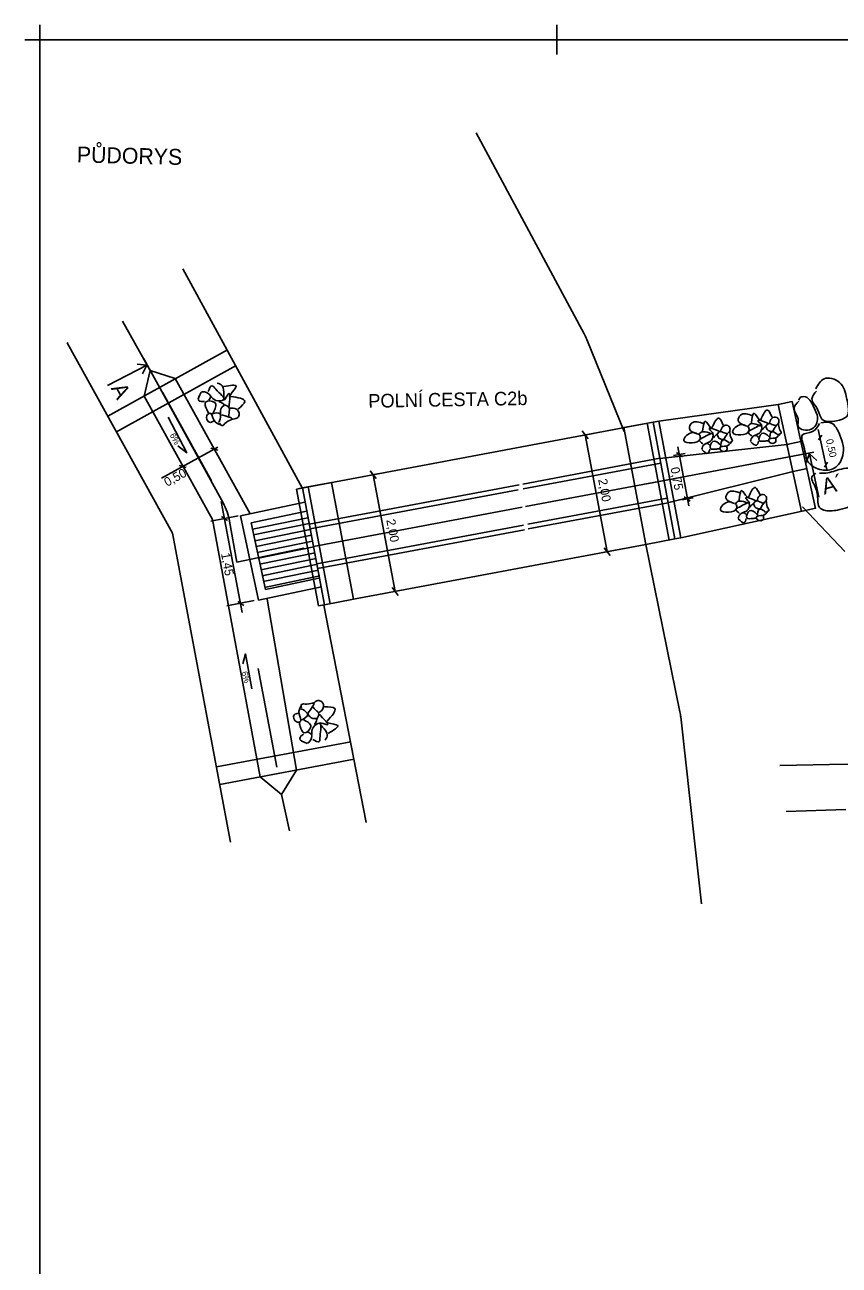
# Model space of a CAD drawing. Extents: x -463095.2 to -463031, y -1105061.3 to -1104976.3.
# Drawn here: x -463091.37 to -463063.97, y -1105018.06 to -1104976.31 of the extents above; entities that cross this region are included whole.
import ezdxf

# ---------------------------------------------------------------- set-up
doc = ezdxf.new("R2010")
doc.units = 0
for name, color, linetype in [('Implicitní', 7, 'Continuous'), ('Vrstva 14', 7, 'Continuous'), ('Vrstva 57', 7, 'Continuous')]:
    doc.layers.add(name, color=color, linetype=linetype)

msp = doc.modelspace()

# ---------------------------------------------------------------- linework, layer by layer
at = {"layer": 'Implicitní'}
for p, q in [((-463073.467, -1104976.311), (-463073.467, -1104977.311)), ((-463073.467, -1104976.311), (-463073.467, -1104977.311)), ((-463073.467, -1104976.311), (-463073.467, -1104977.311)), ((-463073.467, -1104976.311), (-463073.467, -1104977.311)), ((-463072.967, -1104976.811), (-463073.967, -1104976.811)), ((-463072.967, -1104976.811), (-463073.967, -1104976.811)), ((-463072.967, -1104976.811), (-463073.967, -1104976.811)), ((-463072.967, -1104976.811), (-463073.967, -1104976.811))]:
    msp.add_line(p, q, dxfattribs=at)
at = {"layer": 'Vrstva 14'}
for p, q in [((-463090.867, -1104976.311), (-463090.867, -1104977.311)), ((-463090.867, -1104976.311), (-463090.867, -1104977.311)), ((-463090.867, -1104976.312), (-463090.867, -1104977.312)), ((-463091.367, -1104976.811), (-463090.367, -1104976.811)), ((-463091.367, -1104976.811), (-463090.367, -1104976.811)), ((-463091.367, -1104976.812), (-463090.367, -1104976.812)), ((-463072.552, -1104986.71), (-463076.182, -1104979.944)), ((-463082.033, -1104991.9), (-463086.05, -1104984.519)), ((-463087.151, -1104987.945), (-463088.076, -1104986.286)), ((-463071.202, -1104990.001), (-463072.461, -1104986.903)), ((-463084.553, -1104987.255), (-463088.579, -1104989.479)), ((-463087.369, -1104987.55), (-463084.698, -1104992.406)), ((-463084.262, -1104987.782), (-463088.288, -1104990.006)), ((-463087.263, -1104987.762), (-463087.413, -1104988.063)), ((-463086.725, -1104988.7), (-463085.088, -1104991.663)), ((-463066.021, -1104989.094), (-463070.038, -1104989.647)), ((-463065.552, -1104988.991), (-463066.021, -1104989.094)), ((-463066.021, -1104989.094), (-463065.235, -1104992.689)), ((-463065.552, -1104988.991), (-463064.766, -1104992.586)), ((-463082.225, -1104991.937), (-463070.224, -1104989.682)), ((-463071.217, -1104989.868), (-463070.234, -1104989.684)), ((-463070.431, -1104989.721), (-463069.692, -1104993.652)), ((-463070.234, -1104989.684), (-463070.038, -1104989.647)), ((-463070.234, -1104989.684), (-463069.495, -1104993.615)), ((-463070.038, -1104989.647), (-463069.299, -1104993.578)), ((-463072.249, -1104990.062), (-463072.664, -1104990.14)), ((-463072.618, -1104989.979), (-463072.415, -1104990.246)), ((-463071.778, -1104994.044), (-463072.516, -1104990.113)), ((-463071.217, -1104989.868), (-463070.478, -1104993.8)), ((-463064.389, -1104991.275), (-463064.683, -1104989.931)), ((-463064.559, -1104990.118), (-463064.665, -1104990.285)), ((-463086.773, -1104991.571), (-463084.878, -1104990.524)), ((-463084.872, -1104990.63), (-463085.111, -1104990.563)), ((-463065.721, -1104990.436), (-463070.007, -1104990.91)), ((-463069.399, -1104990.515), (-463069.033, -1104992.5)), ((-463065.261, -1104990.336), (-463065.73, -1104990.438)), ((-463074.619, -1104991.769), (-463070.005, -1104990.902)), ((-463069.54, -1104990.808), (-463069.158, -1104990.738)), ((-463069.241, -1104990.851), (-463069.444, -1104990.709)), ((-463064.972, -1104990.749), (-463064.721, -1104990.973)), ((-463085.934, -1104991.21), (-463086.172, -1104991.143)), ((-463079.749, -1104991.319), (-463079.546, -1104991.587)), ((-463074.599, -1104991.928), (-463069.976, -1104991.06)), ((-463065.522, -1104991.345), (-463069.708, -1104992.393)), ((-463065.053, -1104991.242), (-463065.522, -1104991.345)), ((-463064.364, -1104991.031), (-463064.47, -1104991.199)), ((-463081.045, -1104991.716), (-463082.028, -1104991.9)), ((-463074.736, -1104991.792), (-463081.799, -1104993.119)), ((-463081.045, -1104991.716), (-463080.306, -1104995.647)), ((-463080.013, -1104991.522), (-463079.5, -1104991.425)), ((-463078.909, -1104995.384), (-463079.648, -1104991.453)), ((-463074.523, -1104992.525), (-463069.865, -1104991.649)), ((-463082.224, -1104991.937), (-463082.028, -1104991.9)), ((-463082.224, -1104991.937), (-463081.486, -1104995.868)), ((-463082.028, -1104991.9), (-463081.289, -1104995.832)), ((-463081.831, -1104991.863), (-463081.092, -1104995.795)), ((-463074.776, -1104991.962), (-463081.769, -1104993.276)), ((-463074.45, -1104993.122), (-463069.754, -1104992.239)), ((-463069.265, -1104992.303), (-463068.883, -1104992.233)), ((-463068.981, -1104992.344), (-463069.184, -1104992.202)), ((-463084.055, -1104996.094), (-463084.759, -1104992.351)), ((-463084.111, -1104992.843), (-463081.945, -1104992.381)), ((-463074.631, -1104992.545), (-463081.658, -1104993.866)), ((-463074.43, -1104993.281), (-463069.725, -1104992.396)), ((-463069.299, -1104993.578), (-463064.76, -1104992.585)), ((-463063.779, -1104994.043), (-463065.206, -1104992.538)), ((-463084.188, -1104992.842), (-463085.108, -1104993.015)), ((-463084.749, -1104992.856), (-463084.546, -1104992.997)), ((-463083.507, -1104995.679), (-463084.111, -1104992.843)), ((-463083.754, -1104993.073), (-463081.891, -1104992.676)), ((-463083.275, -1104995.323), (-463083.754, -1104993.073)), ((-463081.846, -1104992.903), (-463083.711, -1104993.287)), ((-463084.447, -1105003.822), (-463086.403, -1104993.42)), ((-463081.805, -1104993.099), (-463083.67, -1104993.483)), ((-463081.765, -1104993.295), (-463083.63, -1104993.678)), ((-463081.725, -1104993.49), (-463083.59, -1104993.874)), ((-463074.589, -1104993.148), (-463081.548, -1104994.456)), ((-463074.56, -1104993.305), (-463081.518, -1104994.613)), ((-463081.684, -1104993.686), (-463083.549, -1104994.07)), ((-463081.644, -1104993.882), (-463083.509, -1104994.266)), ((-463070.478, -1104993.8), (-463080.306, -1104995.647)), ((-463070.478, -1104993.8), (-463069.495, -1104993.615)), ((-463070.478, -1104993.8), (-463069.331, -1104999.43)), ((-463069.495, -1104993.615), (-463069.299, -1104993.578)), ((-463081.604, -1104994.078), (-463083.469, -1104994.462)), ((-463081.563, -1104994.274), (-463083.428, -1104994.658)), ((-463071.51, -1104993.993), (-463071.925, -1104994.071)), ((-463071.676, -1104994.177), (-463071.879, -1104993.91)), ((-463081.523, -1104994.47), (-463083.388, -1104994.854)), ((-463081.483, -1104994.666), (-463083.348, -1104995.05)), ((-463081.442, -1104994.862), (-463083.307, -1104995.246)), ((-463083.275, -1104995.323), (-463081.472, -1104994.939)), ((-463083.507, -1104995.679), (-463081.39, -1104995.228)), ((-463079.274, -1104995.453), (-463078.761, -1104995.356)), ((-463078.807, -1104995.518), (-463079.01, -1104995.251)), ((-463083.653, -1104995.692), (-463084.573, -1104995.865)), ((-463084.2, -1104995.716), (-463083.996, -1104995.857)), ((-463081.486, -1104995.868), (-463081.289, -1104995.832)), ((-463081.307, -1104995.845), (-463079.886, -1105003.155)), ((-463080.306, -1104995.647), (-463081.289, -1104995.832)), ((-463082.886, -1105001.301), (-463083.512, -1104997.973)), ((-463069.303, -1104999.609), (-463068.828, -1105003.882)), ((-463080.403, -1105000.44), (-463084.923, -1105001.289)), ((-463080.291, -1105001.031), (-463084.812, -1105001.881)), ((-463082.727, -1105002.219), (-463082.459, -1105003.444)), ((-463063.745, -1105002.725), (-463065.755, -1105002.785)), ((-463068.828, -1105003.882), (-463068.604, -1105005.901))]:
    msp.add_line(p, q, dxfattribs=at)
msp.add_lwpolyline([(-463090.867, -1105060.811), (-463090.867, -1104976.812), (-463031.467, -1104976.812), (-463031.467, -1105060.811)], close=True, dxfattribs=at)
for points in [[(-463089.924, -1104987.024), (-463089.939, -1104987.018), (-463086.403, -1104993.42)], [(-463088.587, -1104988.454), (-463087.263, -1104987.762), (-463087.588, -1104987.728)], [(-463087.151, -1104987.945), (-463087.35, -1104988.805), (-463085.055, -1104992.965)], [(-463087.151, -1104987.945), (-463086.304, -1104988.221), (-463083.789, -1104992.775)], [(-463086.544, -1104989.518), (-463085.919, -1104990.714), (-463086.223, -1104990.485)], [(-463070.387, -1104991.745), (-463064.826, -1104990.694)], [(-463064.653, -1104992.208), (-463064.972, -1104990.749), (-463065.091, -1104991.053)], [(-463082.727, -1105002.219), (-463083.454, -1105001.624), (-463085.055, -1104992.965)], [(-463084.481, -1104993.017), (-463084.235, -1104994.393), (-463081.986, -1104993.931)], [(-463082.727, -1105002.219), (-463082.231, -1105001.396), (-463083.216, -1104995.642)], [(-463083.727, -1104998.656), (-463083.944, -1104997.484), (-463084.028, -1104997.822)], [(-463065.972, -1105001.24), (-463063.741, -1105001.201), (-463054.531, -1105001.611)]]:
    msp.add_lwpolyline(points, dxfattribs=at)
for centre, start, end in [((-463074.314, -1104987.656), 22.1223, 28.2143), ((-463086.45, -1104993.37), 10.1509, 28.8207), ((-463071.291, -1104999.83), 6.3401, 11.5166)]:
    msp.add_arc(centre, 2, start, end, dxfattribs=at)
for points in [[(-463085.2, -1104988.652), (-463085.074, -1104988.462), (-463084.943, -1104988.579), (-463084.68, -1104988.932), (-463084.939, -1104988.954), (-463085.12, -1104988.797)], [(-463084.499, -1104989.209), (-463084.519, -1104988.735), (-463084.653, -1104988.931), (-463084.726, -1104988.459), (-463084.893, -1104988.376)], [(-463084.672, -1104988.482), (-463084.253, -1104988.481), (-463084.449, -1104988.763), (-463084.478, -1104988.834)], [(-463064.736, -1104988.638), (-463064.888, -1104988.896), (-463064.687, -1104989.276), (-463064.553, -1104989.583), (-463064.063, -1104989.637), (-463063.715, -1104989.49), (-463063.715, -1104988.91), (-463063.96, -1104988.352), (-463064.482, -1104988.227), (-463064.759, -1104988.566)], [(-463085.324, -1104988.99), (-463085.516, -1104988.961), (-463085.433, -1104988.673)], [(-463085.172, -1104988.947), (-463085.124, -1104988.814), (-463085.325, -1104988.669), (-463085.422, -1104988.668)], [(-463084.436, -1104988.822), (-463083.967, -1104988.986), (-463084.201, -1104989.248)], [(-463065.328, -1104988.978), (-463065.489, -1104989.223), (-463065.351, -1104989.576), (-463065.351, -1104989.825), (-463064.909, -1104989.919), (-463064.7, -1104989.611), (-463064.833, -1104989.165), (-463065.159, -1104988.826), (-463065.309, -1104988.885), (-463065.325, -1104988.941)], [(-463085.029, -1104989.38), (-463084.979, -1104989.028), (-463085.285, -1104989.01), (-463085.245, -1104989.257), (-463085.181, -1104989.398)], [(-463084.831, -1104989.001), (-463084.663, -1104989.112), (-463084.75, -1104989.199), (-463084.783, -1104989.407)], [(-463084.692, -1104989.091), (-463084.477, -1104989.224), (-463084.49, -1104989.325), (-463084.497, -1104989.532)], [(-463084.487, -1104989.218), (-463084.25, -1104989.247), (-463084.158, -1104989.438), (-463084.232, -1104989.548), (-463084.409, -1104989.579)], [(-463066.61, -1104989.603), (-463066.378, -1104989.281), (-463066.23, -1104989.52)], [(-463084.769, -1104989.776), (-463085.008, -1104989.611), (-463085.134, -1104989.384), (-463085.242, -1104989.457), (-463085.154, -1104989.691), (-463085.007, -1104989.638)], [(-463085.117, -1104989.415), (-463084.794, -1104989.413), (-463084.816, -1104989.64), (-463084.852, -1104989.7)], [(-463084.782, -1104989.434), (-463084.401, -1104989.586), (-463084.597, -1104989.694), (-463084.741, -1104989.802), (-463084.813, -1104989.72)], [(-463068.715, -1104990.088), (-463069.011, -1104989.895), (-463068.938, -1104989.721), (-463068.519, -1104989.74)], [(-463068.566, -1104989.977), (-463068.471, -1104989.654), (-463068.299, -1104989.869), (-463068.251, -1104989.908)], [(-463068.251, -1104989.873), (-463068.018, -1104989.551), (-463067.871, -1104989.79)], [(-463067.074, -1104989.818), (-463067.37, -1104989.626), (-463067.297, -1104989.451), (-463066.879, -1104989.47)], [(-463066.328, -1104989.74), (-463066.696, -1104989.647), (-463066.577, -1104989.794), (-463066.955, -1104989.743), (-463067.057, -1104989.852)], [(-463066.925, -1104989.707), (-463066.83, -1104989.385), (-463066.659, -1104989.599), (-463066.611, -1104989.638)], [(-463066.462, -1104989.861), (-463066.312, -1104989.726), (-463066.237, -1104989.759), (-463066.08, -1104989.812)], [(-463066.318, -1104989.733), (-463066.242, -1104989.557), (-463066.074, -1104989.53), (-463066.007, -1104989.612), (-463066.024, -1104989.755)], [(-463066.22, -1104990.008), (-463066.016, -1104989.75), (-463065.978, -1104989.925), (-463065.929, -1104990.06), (-463066.008, -1104990.097)], [(-463064.638, -1104989.731), (-463064.865, -1104989.999), (-463065.208, -1104990.115), (-463065.159, -1104990.507), (-463064.999, -1104991.047), (-463064.553, -1104991.288), (-463064.143, -1104991.239), (-463063.848, -1104990.806), (-463063.947, -1104990.128), (-463064.259, -1104989.704), (-463064.589, -1104989.704)], [(-463068.658, -1104990.123), (-463068.647, -1104990.248), (-463069.193, -1104990.304), (-463068.902, -1104990.032), (-463068.748, -1104990.079)], [(-463067.969, -1104990.01), (-463068.336, -1104989.917), (-463068.217, -1104990.064), (-463068.595, -1104990.013), (-463068.698, -1104990.122)], [(-463068.555, -1104990.42), (-463068.673, -1104990.28), (-463068.553, -1104990.206), (-463068.223, -1104990.085), (-463068.265, -1104990.289), (-463068.426, -1104990.391)], [(-463068.204, -1104990.217), (-463068.08, -1104990.113), (-463068.034, -1104990.199), (-463067.882, -1104990.272)], [(-463068.103, -1104990.131), (-463067.952, -1104989.996), (-463067.878, -1104990.029), (-463067.72, -1104990.082)], [(-463067.959, -1104990.003), (-463067.883, -1104989.827), (-463067.715, -1104989.8), (-463067.648, -1104989.882), (-463067.664, -1104990.025)], [(-463067.861, -1104990.278), (-463067.657, -1104990.02), (-463067.619, -1104990.195), (-463067.569, -1104990.33), (-463067.648, -1104990.367)], [(-463067.018, -1104989.853), (-463067.007, -1104989.978), (-463067.553, -1104990.034), (-463067.262, -1104989.762), (-463067.108, -1104989.809)], [(-463066.915, -1104990.15), (-463067.032, -1104990.01), (-463066.913, -1104989.936), (-463066.582, -1104989.815), (-463066.624, -1104990.019), (-463066.785, -1104990.122)], [(-463066.682, -1104990.196), (-463066.774, -1104990.129), (-463066.931, -1104990.25), (-463066.954, -1104990.324)], [(-463066.318, -1104990.185), (-463066.576, -1104990.066), (-463066.66, -1104990.297), (-463066.461, -1104990.323), (-463066.339, -1104990.306)], [(-463066.563, -1104989.947), (-463066.44, -1104989.843), (-463066.393, -1104989.929), (-463066.241, -1104990.003)], [(-463065.955, -1104990.076), (-463066.136, -1104990.222), (-463066.339, -1104990.266), (-463066.308, -1104990.366), (-463066.108, -1104990.352), (-463066.115, -1104990.227)], [(-463066.311, -1104990.26), (-463066.239, -1104990.012), (-463066.07, -1104990.081), (-463066.032, -1104990.122)], [(-463068.323, -1104990.466), (-463068.414, -1104990.399), (-463068.571, -1104990.52), (-463068.594, -1104990.594)], [(-463067.958, -1104990.455), (-463068.217, -1104990.336), (-463068.3, -1104990.567), (-463068.102, -1104990.592), (-463067.979, -1104990.575)], [(-463067.596, -1104990.346), (-463067.776, -1104990.492), (-463067.98, -1104990.536), (-463067.948, -1104990.636), (-463067.748, -1104990.622), (-463067.756, -1104990.497)], [(-463067.952, -1104990.53), (-463067.88, -1104990.282), (-463067.711, -1104990.351), (-463067.672, -1104990.392)], [(-463066.684, -1104990.322), (-463066.75, -1104990.463), (-463066.952, -1104990.333)], [(-463068.325, -1104990.592), (-463068.39, -1104990.733), (-463068.592, -1104990.603)], [(-463064.754, -1104991.408), (-463064.883, -1104991.502), (-463064.78, -1104991.859), (-463064.691, -1104992.323), (-463064.642, -1104992.542), (-463064.491, -1104992.644), (-463064.031, -1104992.644), (-463063.394, -1104992.394), (-463063.131, -1104991.993), (-463063.131, -1104991.654), (-463063.389, -1104991.284), (-463063.969, -1104991.284), (-463064.486, -1104991.404), (-463064.629, -1104991.404)], [(-463067.488, -1104992.422), (-463067.784, -1104992.23), (-463067.71, -1104992.055), (-463067.292, -1104992.075)], [(-463066.741, -1104992.344), (-463067.109, -1104992.251), (-463066.99, -1104992.398), (-463067.368, -1104992.347), (-463067.47, -1104992.456)], [(-463067.338, -1104992.311), (-463067.243, -1104991.989), (-463067.072, -1104992.203), (-463067.024, -1104992.242)], [(-463067.024, -1104992.208), (-463066.791, -1104991.885), (-463066.644, -1104992.125)], [(-463066.732, -1104992.337), (-463066.655, -1104992.161), (-463066.488, -1104992.135), (-463066.42, -1104992.217), (-463066.437, -1104992.359)], [(-463067.431, -1104992.457), (-463067.42, -1104992.583), (-463067.966, -1104992.638), (-463067.675, -1104992.367), (-463067.521, -1104992.413)], [(-463067.328, -1104992.754), (-463067.446, -1104992.614), (-463067.326, -1104992.541), (-463066.995, -1104992.419), (-463067.037, -1104992.623), (-463067.198, -1104992.726)], [(-463066.731, -1104992.789), (-463066.989, -1104992.67), (-463067.073, -1104992.901), (-463066.874, -1104992.927), (-463066.752, -1104992.91)], [(-463066.976, -1104992.551), (-463066.853, -1104992.447), (-463066.806, -1104992.534), (-463066.655, -1104992.607)], [(-463066.875, -1104992.465), (-463066.725, -1104992.331), (-463066.65, -1104992.364), (-463066.493, -1104992.416)], [(-463066.724, -1104992.864), (-463066.652, -1104992.616), (-463066.483, -1104992.686), (-463066.445, -1104992.726)], [(-463066.634, -1104992.612), (-463066.43, -1104992.355), (-463066.391, -1104992.53), (-463066.342, -1104992.665), (-463066.421, -1104992.701)], [(-463067.095, -1104992.8), (-463067.187, -1104992.733), (-463067.344, -1104992.854), (-463067.367, -1104992.928)], [(-463067.097, -1104992.926), (-463067.163, -1104993.067), (-463067.365, -1104992.937)], [(-463066.368, -1104992.68), (-463066.549, -1104992.826), (-463066.752, -1104992.871), (-463066.721, -1104992.97), (-463066.521, -1104992.956), (-463066.528, -1104992.831)], [(-463082.063, -1104999.225), (-463082.143, -1104999.505), (-463082.095, -1104999.76), (-463082.225, -1104999.773), (-463082.306, -1104999.536), (-463082.159, -1104999.484)], [(-463082.102, -1104999.725), (-463081.851, -1104999.521), (-463082.014, -1104999.361), (-463082.079, -1104999.336)], [(-463081.856, -1104999.498), (-463081.659, -1104999.137), (-463081.879, -1104999.179), (-463082.058, -1104999.188), (-463082.062, -1104999.296)], [(-463081.569, -1104999.704), (-463081.487, -1104999.465), (-463081.561, -1104999.396), (-463081.698, -1104999.24)], [(-463081.491, -1104999.476), (-463081.327, -1104999.303), (-463081.378, -1104999.096), (-463081.505, -1104999.059), (-463081.661, -1104999.148)], [(-463081.2, -1104999.749), (-463080.942, -1104999.324), (-463081.29, -1104999.271)], [(-463082.012, -1104999.696), (-463081.749, -1104999.936), (-463081.974, -1105000.145), (-463082.1, -1104999.928), (-463082.141, -1104999.779)], [(-463081.618, -1104999.862), (-463081.559, -1104999.67), (-463081.681, -1104999.658), (-463081.839, -1104999.519)], [(-463081.495, -1104999.491), (-463081.208, -1104999.868), (-463081.436, -1104999.803), (-463081.192, -1105000.213), (-463081.268, -1105000.384)], [(-463081.846, -1105000.121), (-463081.725, -1105000.194), (-463081.788, -1105000.433), (-463081.861, -1105000.496)], [(-463081.68, -1105000.366), (-463081.462, -1105000.433), (-463081.436, -1105000.259), (-463081.457, -1104999.82), (-463081.672, -1104999.968), (-463081.711, -1105000.203)], [(-463081.165, -1105000.162), (-463080.841, -1104999.895), (-463081.172, -1104999.803), (-463081.239, -1104999.767)], [(-463081.991, -1105000.185), (-463082.121, -1105000.329), (-463081.873, -1105000.498)]]:
    msp.add_spline(points, degree=3, dxfattribs=at)

# ---------------------------------------------------------------- texts
for s, height, rotation, p in [('PŮDORYS', 0.536, 358.5898, (-463089.622, -1104980.942)), ('A', 0.536, 297.5844, (-463088.481, -1104988.541)), ('0,50', 0.24, 282.3388, (-463064.419, -1104990.279)), ('0,50', 0.3, 28.9139, (-463086.579, -1104991.864)), ('0,75', 0.3, 280.4302, (-463069.648, -1104991.226)), ('2,00', 0.3, 280.6452, (-463072.081, -1104991.619)), ('A´', 0.536, 14.398, (-463064.48, -1104992.127)), ('2,00', 0.3, 280.6452, (-463079.208, -1104992.979)), ('1,45', 0.3, 280.6452, (-463084.769, -1104994.111))]:
    msp.add_text(s, height=height, rotation=rotation, dxfattribs=at).set_placement(p)
at = {"layer": 'Vrstva 57'}
for s, height, rotation, p in [('POLNÍ CESTA C2b', 0.459, 0.9997, (-463079.81, -1104989.201)), ('6%', 0.204, 297.5844, (-463086.499, -1104990.12)), ('6%', 0.204, 283.5402, (-463084.077, -1104998.099))]:
    msp.add_text(s, height=height, rotation=rotation, dxfattribs=at).set_placement(p)

doc.saveas('drawing.dxf')
